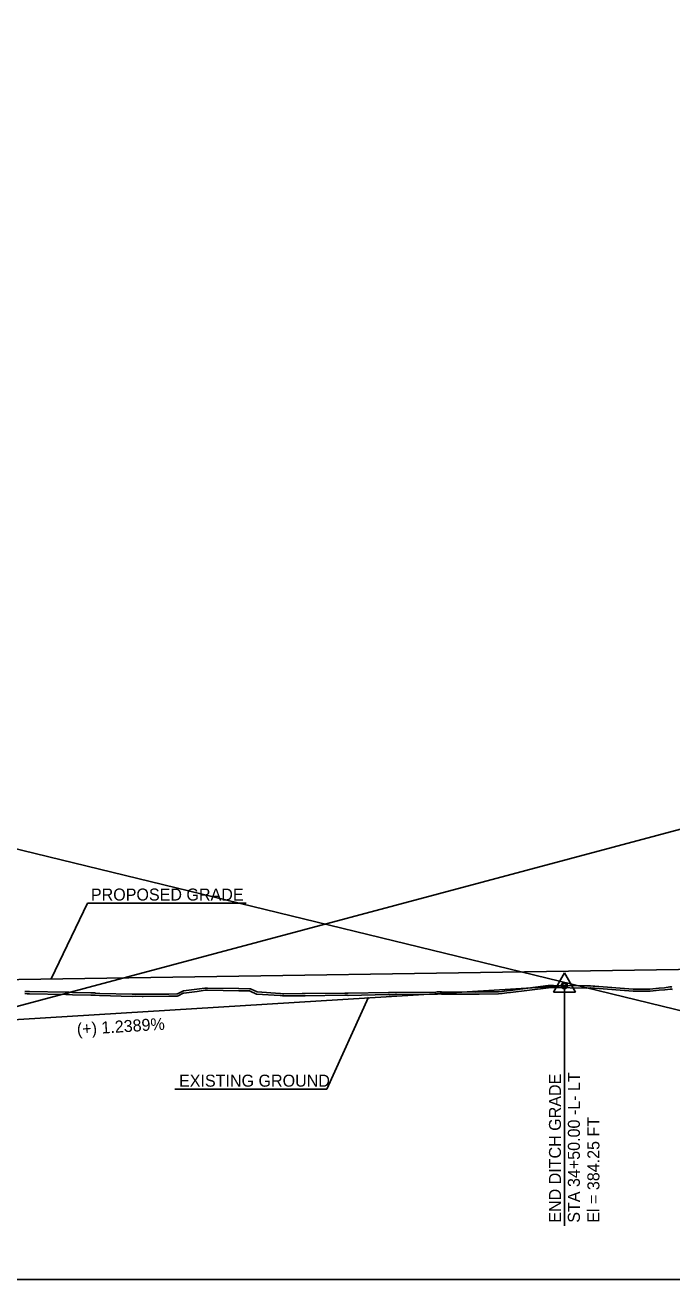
# Model space of a CAD drawing. Extents: x 1625686 to 1640492, y 1161393 to 1175642.
# Drawn here: x 1638048 to 1638424, y 1174911 to 1175642 of the extents above; entities that cross this region are included whole.
import ezdxf

# ---------------------------------------------------------------- set-up
doc = ezdxf.new("R2010")
doc.units = 0
for name, color, linetype in [('Exist Profile Cell', 7, 'Continuous'), ('Prop Vertical Profile Ditch Grade Left', 7, 'Continuous'), ('Prop Vertical Profile Ditch Grade Left Label', 7, 'Continuous'), ('Prop Vertical Profile Grade', 7, 'Continuous'), ('Prop VPI Ditch Grade Left Label', 7, 'Continuous'), ('Prop VPI Label', 7, 'Continuous'), ('Scratch_Level_1', 7, 'Continuous'), ('Scratch_Level_3', 7, 'Continuous')]:
    doc.layers.add(name, color=color, linetype=linetype)

msp = doc.modelspace()

# ---------------------------------------------------------------- linework, layer by layer
at = {"layer": 'Exist Profile Cell'}
msp.add_line((1635911.78, 1174910.79), (1640378.1, 1174910.79), dxfattribs=at)
at = {"layer": 'Prop Vertical Profile Ditch Grade Left'}
msp.add_line((1637846.02, 1175050.09), (1638361.78, 1175082.04), dxfattribs=at)
at = {"layer": 'Prop Vertical Profile Grade'}
msp.add_line((1638011.78, 1175085.25), (1638636.78, 1175094.7), dxfattribs=at)
at = {"layer": 'Prop VPI Ditch Grade Left Label'}
for p, q in [((1638361.78, 1175089.52), (1638355.33, 1175078.32)), ((1638361.78, 1175089.52), (1638368.28, 1175078.32)), ((1638361.78, 1175082.04), (1638361.78, 1174951.57)), ((1638355.33, 1175078.32), (1638368.28, 1175078.32)), ((1638361.78, 1175072.54), (1638361.78, 1174942.07))]:
    msp.add_line(p, q, dxfattribs=at)
for radius in [1.75, 1.2]:
    msp.add_circle((1638361.78, 1175082.04), radius, dxfattribs=at)
at = {"layer": 'Prop VPI Label'}
for p, q in [((1638083.91, 1175130.23), (1638062.88, 1175086.03)), ((1638176.46, 1175130.23), (1638083.91, 1175130.23)), ((1638223.4, 1175021.72), (1638247.58, 1175075.37)), ((1638223.4, 1175021.72), (1638134.79, 1175021.72))]:
    msp.add_line(p, q, dxfattribs=at)
at = {"layer": 'Scratch_Level_1'}
for p, q in [((1638152.73, 1175080.63), (1638153.93, 1175080.63)), ((1638152.73, 1175079.38), (1638153.93, 1175079.38)), ((1638153.95, 1175079.38), (1638172.1, 1175079.09)), ((1638153.97, 1175080.63), (1638172.12, 1175080.34)), ((1638172.12, 1175080.34), (1638178.33, 1175080.23)), ((1638352.51, 1175082.08), (1638353.63, 1175082.15)), ((1638352.58, 1175080.83), (1638353.71, 1175080.9)), ((1638353.78, 1175080.9), (1638355.39, 1175080.9)), ((1638353.79, 1175082.15), (1638355.4, 1175082.15)), ((1638423.72, 1175080.05), (1638424.15, 1175079.97)), ((1638423.95, 1175081.28), (1638424.37, 1175081.2)), ((1638424.18, 1175079.97), (1638424.82, 1175079.84)), ((1638050.17, 1175077.34), (1638071.35, 1175077)), ((1638050.19, 1175078.59), (1638071.37, 1175078.25)), ((1638071.37, 1175077), (1638073.17, 1175076.94)), ((1638071.41, 1175078.25), (1638073.21, 1175078.19)), ((1638085.97, 1175076.6), (1638088.33, 1175076.53)), ((1638086.01, 1175077.85), (1638088.37, 1175077.78)), ((1638172.1, 1175079.09), (1638178.31, 1175078.98)), ((1638198.25, 1175077.35), (1638208.98, 1175077.44)), ((1638198.27, 1175076.1), (1638208.99, 1175076.19)), ((1638208.99, 1175077.44), (1638209.88, 1175077.45)), ((1638209, 1175076.19), (1638209.89, 1175076.2)), ((1638287.85, 1175078.43), (1638288.92, 1175078.46)), ((1638287.88, 1175077.18), (1638288.95, 1175077.21))]:
    msp.add_line(p, q, dxfattribs=at)
for points in [[(1638139.97, 1175078.97), (1638147.64, 1175079.93), (1638152.37, 1175080.6)], [(1638140.13, 1175077.73), (1638147.81, 1175078.69), (1638152.55, 1175079.37)], [(1638179.34, 1175080), (1638182.75, 1175078.41), (1638196.22, 1175077.48)], [(1638328.21, 1175079.11), (1638330.17, 1175079.25), (1638352.34, 1175082.06)], [(1638328.3, 1175077.86), (1638330.3, 1175078), (1638352.5, 1175080.82)], [(1638355.41, 1175080.9), (1638374.59, 1175080.62), (1638376.73, 1175080.71)], [(1638355.43, 1175082.15), (1638374.57, 1175081.87), (1638376.68, 1175081.95)], [(1638376.88, 1175080.7), (1638378.41, 1175080.59), (1638379.29, 1175080.53)], [(1638376.97, 1175081.95), (1638378.5, 1175081.83), (1638379.38, 1175081.77)], [(1638379.3, 1175080.53), (1638401.76, 1175078.85), (1638402.75, 1175078.81), (1638410.51, 1175078.84)], [(1638379.39, 1175081.77), (1638401.83, 1175080.09), (1638402.77, 1175080.06), (1638410.51, 1175080.09)], [(1638410.52, 1175080.09), (1638411.62, 1175080.09), (1638416.85, 1175080.68)], [(1638410.52, 1175078.84), (1638411.69, 1175078.84), (1638416.99, 1175079.44)], [(1638416.97, 1175080.69), (1638420.09, 1175080.88), (1638423.17, 1175081.3)], [(1638417.05, 1175079.44), (1638420.21, 1175079.64), (1638423.34, 1175080.06)], [(1638047.58, 1175077.43), (1638048.8, 1175077.36), (1638050.17, 1175077.34)], [(1638047.66, 1175078.68), (1638048.85, 1175078.6), (1638050.18, 1175078.59)], [(1638073.23, 1175076.94), (1638075.22, 1175076.79), (1638085.96, 1175076.6)], [(1638073.33, 1175078.19), (1638075.28, 1175078.04), (1638085.98, 1175077.85)], [(1638088.42, 1175076.52), (1638091.04, 1175076.24), (1638110.02, 1175075.82), (1638111.78, 1175075.88)], [(1638088.56, 1175077.76), (1638091.12, 1175077.49), (1638110.01, 1175077.08), (1638111.74, 1175077.13)], [(1638111.84, 1175075.88), (1638115.77, 1175075.79), (1638116.44, 1175075.77), (1638131.42, 1175075.88), (1638136.16, 1175075.97), (1638136.77, 1175076.08), (1638139.7, 1175077.6)], [(1638111.87, 1175077.13), (1638115.8, 1175077.04), (1638116.45, 1175077.02), (1638131.4, 1175077.13), (1638136.04, 1175077.22), (1638136.37, 1175077.27), (1638139.13, 1175078.71)], [(1638178.81, 1175078.87), (1638182.43, 1175077.18), (1638196.14, 1175076.23)], [(1638196.22, 1175076.23), (1638197.55, 1175076.05), (1638198.19, 1175076.09)], [(1638196.38, 1175077.46), (1638197.59, 1175077.3), (1638198.1, 1175077.34)], [(1638209.89, 1175077.45), (1638210.84, 1175077.45), (1638233.81, 1175077.67)], [(1638209.89, 1175076.2), (1638210.84, 1175076.2), (1638233.82, 1175076.42)], [(1638233.81, 1175077.67), (1638234.43, 1175077.68), (1638235.08, 1175077.69)], [(1638233.82, 1175076.42), (1638234.44, 1175076.43), (1638235.1, 1175076.44)], [(1638235.17, 1175076.44), (1638235.8, 1175076.41), (1638259.36, 1175076.82)], [(1638235.22, 1175077.69), (1638235.81, 1175077.66), (1638259.34, 1175078.07)], [(1638259.45, 1175076.82), (1638259.91, 1175076.8), (1638260.4, 1175076.79), (1638263.38, 1175076.82), (1638263.98, 1175076.85)], [(1638259.51, 1175078.07), (1638259.95, 1175078.05), (1638260.41, 1175078.04), (1638263.35, 1175078.07), (1638263.93, 1175078.1)], [(1638264.01, 1175078.1), (1638286.83, 1175078.36), (1638287.73, 1175078.43)], [(1638264.03, 1175076.85), (1638286.88, 1175077.11), (1638287.82, 1175077.18)], [(1638289, 1175077.21), (1638290.17, 1175077.19), (1638310.12, 1175077.07), (1638312.05, 1175077.13)], [(1638289.02, 1175078.46), (1638290.19, 1175078.44), (1638310.11, 1175078.32), (1638312.01, 1175078.38)], [(1638312.06, 1175078.38), (1638323.38, 1175078.55), (1638325.32, 1175078.75), (1638328.08, 1175079.09)], [(1638312.07, 1175077.13), (1638323.45, 1175077.3), (1638325.46, 1175077.51), (1638328.23, 1175077.85)]]:
    msp.add_lwpolyline(points, dxfattribs=at)
for centre, radius, start, end in [((1638152.73, 1175078.13), 2.5, 90.05967, 98.14747), ((1638152.73, 1175078.13), 1.25, 90.05967, 98.14747), ((1638153.93, 1175078.13), 2.5, 89.07407, 90.05967), ((1638153.93, 1175078.13), 1.25, 89.07407, 90.05967), ((1638172.08, 1175077.84), 2.5, 89.04563, 89.07407), ((1638178.29, 1175077.73), 2.5, 65.04284, 89.04563), ((1638352.65, 1175079.58), 2.5, 93.36817, 97.24395), ((1638352.65, 1175079.58), 1.25, 93.36817, 97.24395), ((1638353.78, 1175079.65), 2.5, 89.82003, 93.36817), ((1638353.78, 1175079.65), 1.25, 89.82003, 93.36817), ((1638355.39, 1175079.65), 1.25, 89.16366, 89.82003), ((1638355.39, 1175079.65), 2.5, 89.16366, 89.82003), ((1638376.79, 1175079.46), 2.5, 85.68398, 92.38584), ((1638376.79, 1175079.46), 1.25, 85.68398, 92.38584), ((1638379.21, 1175079.28), 1.25, 85.7228, 85.99209), ((1638379.21, 1175079.28), 2.5, 85.7228, 85.99209), ((1638410.52, 1175077.59), 2.5, 89.87813, 90.19099), ((1638417.13, 1175078.2), 2.5, 93.54147, 96.48366), ((1638417.13, 1175078.2), 1.25, 93.54147, 96.48366), ((1638423.5, 1175078.82), 2.5, 79.73938, 97.63681), ((1638423.5, 1175078.82), 1.25, 79.73938, 97.63681), ((1638423.92, 1175078.74), 1.25, 78.37168, 79.73938), ((1638423.92, 1175078.74), 2.5, 78.37168, 79.73938), ((1638047.51, 1175076.18), 2.5, 86.55045, 90.27052), ((1638050.15, 1175076.09), 1.25, 89.08519, 89.24887), ((1638050.15, 1175076.09), 2.5, 89.08519, 89.24887), ((1638071.33, 1175075.75), 1.25, 88.27572, 89.08519), ((1638071.33, 1175075.75), 2.5, 88.27572, 89.08519), ((1638073.14, 1175075.7), 1.25, 85.59497, 88.27572), ((1638073.14, 1175075.7), 2.5, 85.59497, 88.27572), ((1638085.93, 1175075.35), 1.25, 88.22616, 88.99259), ((1638085.93, 1175075.35), 2.5, 88.22616, 88.99259), ((1638088.29, 1175075.28), 1.25, 83.84734, 88.22616), ((1638088.29, 1175075.28), 2.5, 83.84734, 88.22616), ((1638111.81, 1175074.63), 2.5, 88.65335, 91.76912), ((1638111.81, 1175074.63), 1.25, 88.65335, 91.76912), ((1638140.28, 1175076.49), 2.5, 97.10067, 117.45466), ((1638140.28, 1175076.49), 1.25, 97.10067, 117.45466), ((1638172.08, 1175077.84), 1.25, 89.04563, 89.07407), ((1638178.29, 1175077.73), 1.25, 65.04284, 89.04563), ((1638196.05, 1175074.99), 1.25, 82.43545, 86.03259), ((1638196.05, 1175074.99), 2.5, 82.43545, 86.03259), ((1638198.28, 1175074.85), 2.5, 90.52342, 93.95641), ((1638198.28, 1175074.85), 1.25, 90.52342, 93.95641), ((1638209.01, 1175074.94), 2.5, 90.41359, 90.52342), ((1638209.01, 1175074.94), 1.25, 90.41359, 90.52342), ((1638209.9, 1175074.95), 2.5, 90.24414, 90.41359), ((1638209.9, 1175074.95), 1.25, 90.24414, 90.41359), ((1638233.83, 1175075.17), 2.5, 90.51451, 90.54233), ((1638233.83, 1175075.17), 1.25, 90.51451, 90.54233), ((1638235.12, 1175075.19), 2.5, 87.60294, 90.87641), ((1638235.12, 1175075.19), 1.25, 87.60294, 90.87641), ((1638259.38, 1175075.58), 2.5, 86.98867, 91.00897), ((1638259.38, 1175075.58), 1.25, 86.98867, 91.00897), ((1638264.04, 1175075.6), 2.5, 90.6594, 92.67211), ((1638264.04, 1175075.6), 1.25, 90.6594, 92.67211), ((1638287.91, 1175075.93), 2.5, 91.24041, 94.10572), ((1638287.91, 1175075.93), 1.25, 91.24041, 94.10572), ((1638288.98, 1175075.96), 2.5, 89.00503, 91.24041), ((1638288.98, 1175075.96), 1.25, 89.00503, 91.24041), ((1638312.09, 1175075.88), 2.5, 90.84585, 91.875), ((1638312.09, 1175075.88), 1.25, 90.84585, 91.875), ((1638328.39, 1175076.61), 2.5, 94.10761, 97.11024), ((1638328.39, 1175076.61), 1.25, 94.10761, 97.11024), ((1638410.52, 1175077.59), 1.25, 89.87813, 90.19099)]:
    msp.add_arc(centre, radius, start, end, dxfattribs=at)
at = {"layer": 'Scratch_Level_3'}
for p, q in [((1636069.38, 1175641.97), (1640127.74, 1174654.21)), ((1636080.34, 1174544.46), (1640138.71, 1175631))]:
    msp.add_line(p, q, dxfattribs=at)
msp.add_lwpolyline([(1635911.78, 1174910.79), (1640049.19, 1174910.79), (1640049.19, 1175362.47)], dxfattribs=at)

# ---------------------------------------------------------------- texts
at = {"layer": 'Prop Vertical Profile Ditch Grade Left Label'}
msp.add_text('(+) 1.2389%', height=7, rotation=3.5448, dxfattribs=at).set_placement((1638078.02, 1175053.22))
at = {"layer": 'Prop VPI Ditch Grade Left Label'}
for s, p in [('END DITCH GRADE', (1638359.78, 1174943.88)), ('STA 34+50.00 -L- LT', (1638370.78, 1174943.88)), ('El = 384.25 FT', (1638382.16, 1174943.88))]:
    msp.add_text(s, height=7, rotation=90, dxfattribs=at).set_placement(p)
at = {"layer": 'Prop VPI Label'}
for s, p in [('PROPOSED GRADE', (1638085.96, 1175131.67)), ('EXISTING GROUND', (1638137.31, 1175023.17))]:
    msp.add_text(s, height=7, dxfattribs=at).set_placement(p)

doc.saveas('drawing.dxf')
